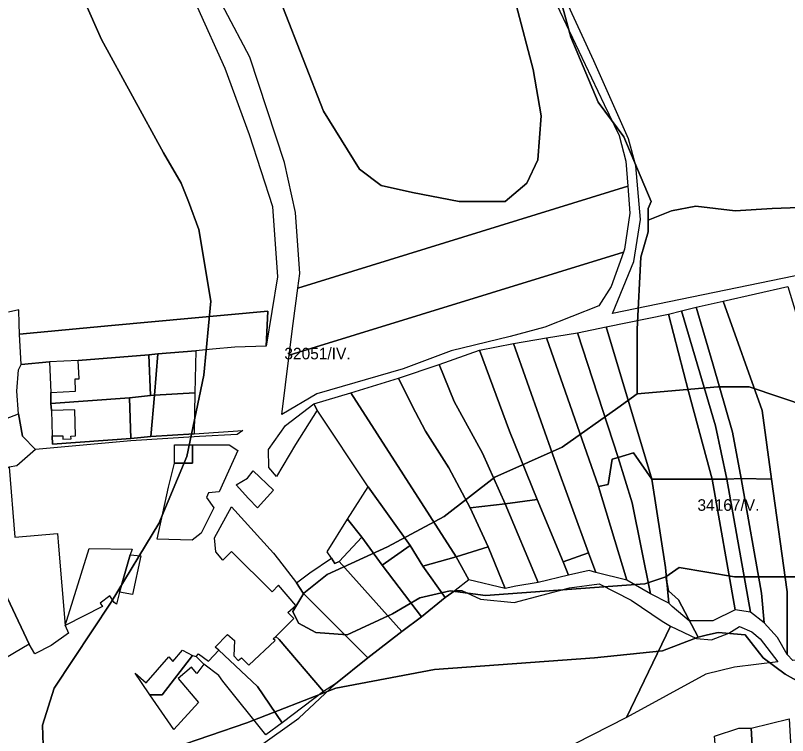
# Model space of a CAD drawing. Extents: x -532083 to -529270, y -1180561 to -1176456.
# Drawn here: x -531885.3 to -531552, y -1178230.5 to -1177919.6 of the extents above; entities that cross this region are included whole.
import ezdxf

# ---------------------------------------------------------------- set-up
doc = ezdxf.new("R2010")
doc.units = 0
for name, color, linetype in [('95560013', 7, 'Continuous'), ('95590013', 7, 'Continuous'), ('95610013', 7, 'Continuous'), ('95660013', 7, 'Continuous')]:
    doc.layers.add(name, color=color, linetype=linetype)

msp = doc.modelspace()

# ---------------------------------------------------------------- linework, layer by layer
at = {"layer": '95560013'}
for points in [[(-531424.6003, -1177849.79445), (-531429.9573, -1177919.79245), (-531429.9573, -1177963.95745), (-531425.3063, -1178000.34745), (-531424.6863, -1178005.32445), (-531490.1123, -1178018.25145), (-531539.5053, -1178030.11045), (-531627.5183, -1178048.29445), (-531618.3223, -1178025.89345), (-531615.4323, -1178007.71045), (-531617.5343, -1177984.51945), (-531620.6873, -1177972.92345), (-531635.6623, -1177939.19145), (-531648.2733, -1177911.52045)], [(-531806.8203, -1177915.90545), (-531794.8753, -1177942.31245), (-531784.4443, -1177970.98845), (-531774.3943, -1178002.04445), (-531772.2003, -1178032.42445), (-531777.0283, -1178062.36345), (-531776.2963, -1178047.24745), (-531843.8873, -1178053.43645), (-531883.5303, -1178057.25145), (-531883.6763, -1178052.70245), (-531883.8673, -1178046.75645), (-531888.2813, -1178047.78945)]]:
    msp.add_lwpolyline(points, dxfattribs=at)
for points in [[(-531633.5823, -1178122.95245), (-531656.0973, -1178058.76345), (-531642.7123, -1178056.59445), (-531625.1133, -1178110.40845), (-531627.7023, -1178111.15745), (-531629.4663, -1178122.16545)], [(-531836.0653, -1178084.78645), (-531869.9413, -1178087.19945), (-531869.9983, -1178082.36545), (-531859.3073, -1178081.88145), (-531859.5493, -1178076.52245), (-531857.8333, -1178076.44445), (-531858.1913, -1178068.55145), (-531827.6463, -1178066.08745), (-531827.0453, -1178083.78145)], [(-531807.8023, -1178082.57445), (-531825.2413, -1178083.58045), (-531823.8383, -1178065.68545), (-531807.4013, -1178064.47845)], [(-531826.8443, -1178101.47545), (-531835.4643, -1178102.27945), (-531836.0653, -1178084.78645), (-531827.0453, -1178083.78145), (-531825.2413, -1178083.58045)], [(-531808.2023, -1178100.26845), (-531826.8443, -1178101.47545), (-531825.2413, -1178083.58045), (-531807.8023, -1178082.57445)], [(-531835.4643, -1178102.27945), (-531869.3403, -1178104.69245), (-531869.3973, -1178101.18845), (-531864.9013, -1178101.06545), (-531864.8613, -1178102.54245), (-531861.2943, -1178102.44545), (-531861.3283, -1178101.19745), (-531859.3323, -1178101.14345), (-531859.6393, -1178089.92145), (-531869.6983, -1178090.19545), (-531869.9413, -1178087.19945), (-531836.0653, -1178084.78645)]]:
    msp.add_lwpolyline(points, close=True, dxfattribs=at)
at = {"layer": '95590013'}
for points in [[(-531558.9753, -1178119.80545), (-531572.0323, -1178119.52045), (-531575.7223, -1178099.58945), (-531584.2383, -1178069.97645), (-531591.4943, -1178045.51745), (-531579.8623, -1178043.01645), (-531562.9493, -1178090.19245)], [(-531807.4013, -1178064.47845), (-531823.8383, -1178065.68545), (-531827.6463, -1178066.08745), (-531858.1913, -1178068.55145), (-531870.5983, -1178069.11445), (-531882.8463, -1178070.37345), (-531883.5303, -1178057.25145), (-531843.8873, -1178053.43645), (-531776.2963, -1178047.24745), (-531777.0283, -1178062.36345), (-531790.5263, -1178062.82645), (-531800.1913, -1178063.69345)], [(-531584.5223, -1178119.80545), (-531610.6373, -1178119.80545), (-531630.2673, -1178054.12845), (-531603.4033, -1178048.57245), (-531594.7413, -1178081.93545)], [(-531618.5853, -1178108.41545), (-531625.1133, -1178110.40845), (-531642.7123, -1178056.59445), (-531630.2673, -1178054.12845), (-531610.6373, -1178119.80545)], [(-531673.9533, -1178130.42245), (-531683.7643, -1178108.67545), (-531695.9463, -1178086.30845), (-531702.3463, -1178070.36145), (-531685.0033, -1178064.14845), (-531671.9953, -1178099.14845), (-531660.0393, -1178128.65345)], [(-531648.8683, -1178155.58445), (-531660.0393, -1178128.65345), (-531671.9953, -1178099.14845), (-531685.0033, -1178064.14845), (-531670.3443, -1178061.24845), (-531652.5873, -1178111.36745), (-531637.8933, -1178151.65345)], [(-531825.2413, -1178083.58045), (-531827.0453, -1178083.78145), (-531827.6463, -1178066.08745), (-531823.8383, -1178065.68545)], [(-531876.5863, -1178106.95645), (-531882.3023, -1178101.22345), (-531883.9353, -1178091.66845), (-531884.7513, -1178081.83945), (-531883.9353, -1178072.55745), (-531882.8463, -1178070.37345), (-531870.5983, -1178069.11445), (-531869.9983, -1178082.36545), (-531869.9413, -1178087.19945), (-531869.6983, -1178090.19545), (-531869.3973, -1178101.18845), (-531869.3403, -1178104.69245), (-531835.4643, -1178102.27945), (-531826.8443, -1178101.47545), (-531808.2023, -1178100.26845), (-531787.1773, -1178098.75445), (-531789.5383, -1178100.57645), (-531805.7973, -1178101.47545), (-531835.4643, -1178103.28445)], [(-531681.2053, -1178149.09745), (-531695.1193, -1178153.42245), (-531740.5423, -1178082.58045), (-531719.8963, -1178076.16045), (-531714.1153, -1178088.17245), (-531708.3343, -1178099.14845), (-531698.2173, -1178114.88845), (-531689.0443, -1178132.19145)], [(-531709.4263, -1178157.35445), (-531714.9403, -1178148.43845), (-531733.1103, -1178123.17245), (-531754.9953, -1178090.03645), (-531756.4403, -1178087.34345), (-531740.5423, -1178082.58045), (-531695.1193, -1178153.42245)], [(-531912.2403, -1178121.42645), (-531943.5403, -1178133.16545), (-531957.9653, -1178137.80645), (-531968.3253, -1178140.92145), (-531972.2873, -1178128.08345), (-531979.3313, -1178130.25745), (-531975.3683, -1178143.09545), (-531989.5373, -1178147.08845), (-531996.6133, -1178129.61645), (-531923.9443, -1178105.04545), (-531905.1643, -1178099.03945), (-531891.8283, -1178094.67145), (-531887.7453, -1178093.03345), (-531883.9353, -1178091.66845), (-531882.3023, -1178101.22345), (-531876.5863, -1178106.95645), (-531884.7513, -1178114.05445), (-531888.0173, -1178114.60045), (-531899.4483, -1178117.33145)], [(-531808.9713, -1178146.12145), (-531824.1483, -1178145.71645), (-531819.2383, -1178123.31745), (-531816.6083, -1178112.86745), (-531808.9213, -1178112.86745), (-531808.9213, -1178104.95345), (-531792.9893, -1178104.94845), (-531789.3563, -1178107.49945), (-531797.3483, -1178125.35245), (-531801.8883, -1178125.71745), (-531802.7963, -1178127.72145), (-531799.7093, -1178132.27545), (-531805.1573, -1178143.20645)], [(-531808.9213, -1178112.86745), (-531816.6083, -1178112.86745), (-531816.6083, -1178104.95345), (-531808.9213, -1178104.95345)], [(-531621.4313, -1178163.44845), (-531633.5823, -1178122.95245), (-531629.4663, -1178122.16545), (-531627.7023, -1178111.15745), (-531625.1133, -1178110.40845), (-531619.1523, -1178130.05545), (-531611.2043, -1178169.34845)], [(-531611.2043, -1178169.34845), (-531619.1523, -1178130.05545), (-531625.1133, -1178110.40845), (-531618.5853, -1178108.41545), (-531610.6373, -1178119.80545), (-531604.6763, -1178157.95945), (-531603.2563, -1178173.33445)], [(-531879.4333, -1178191.11245), (-531912.2403, -1178121.42645), (-531899.4483, -1178117.33145), (-531888.0173, -1178114.60045), (-531885.5763, -1178144.90545), (-531867.1183, -1178143.26045), (-531866.7063, -1178148.80945), (-531863.7823, -1178183.03145), (-531862.3773, -1178186.29845), (-531869.9033, -1178191.70845), (-531876.8763, -1178195.29845)], [(-531604.6763, -1178157.95945), (-531610.6373, -1178119.80545), (-531584.5223, -1178119.80545), (-531574.5873, -1178176.18145), (-531584.2383, -1178181.02245), (-531594.4573, -1178181.02245), (-531601.8373, -1178174.75845), (-531603.2563, -1178173.33445)], [(-531574.5873, -1178176.18145), (-531584.5223, -1178119.80545), (-531578.2773, -1178119.80545), (-531568.0583, -1178177.32045)], [(-531568.0583, -1178177.32045), (-531578.2773, -1178119.80545), (-531572.0323, -1178119.52045), (-531563.2323, -1178169.06345), (-531562.0973, -1178181.87645)], [(-531563.2323, -1178169.06345), (-531572.0323, -1178119.52045), (-531558.9753, -1178119.80545), (-531552.1623, -1178168.49445), (-531552.1623, -1178195.54345), (-531556.4203, -1178188.14045), (-531562.0973, -1178181.87645)], [(-531879.4333, -1178191.11245), (-531903.0633, -1178205.09745), (-531924.6193, -1178170.74745), (-531929.2293, -1178162.13145), (-531943.5403, -1178133.16545), (-531912.2403, -1178121.42645)], [(-531673.9533, -1178166.98645), (-531681.2053, -1178149.09745), (-531689.0443, -1178132.19145), (-531673.9533, -1178130.42245), (-531659.6473, -1178164.43045), (-531669.2503, -1178166.00345)], [(-531659.6473, -1178164.43045), (-531673.9533, -1178130.42245), (-531660.0393, -1178128.65345), (-531648.8683, -1178155.58445), (-531646.5163, -1178161.28545)], [(-531752.3743, -1178211.55845), (-531771.5303, -1178189.07745), (-531772.8423, -1178187.81645), (-531765.1443, -1178180.06045), (-531767.7793, -1178177.44445), (-531764.2333, -1178174.43745), (-531771.7133, -1178165.65445), (-531774.5073, -1178168.43345), (-531792.0313, -1178151.03945), (-531795.8253, -1178154.86245), (-531798.8033, -1178151.21445), (-531799.4213, -1178145.21745), (-531792.0013, -1178131.77745), (-531773.8613, -1178151.83445), (-531771.7993, -1178154.52245), (-531763.9663, -1178164.65445), (-531761.0803, -1178168.99645), (-531733.1243, -1178196.99145), (-531747.1753, -1178208.14145)], [(-531718.4433, -1178185.63145), (-531745.6203, -1178155.34945), (-531735.7263, -1178144.80445), (-531727.0683, -1178157.00345), (-531710.0543, -1178179.32045)], [(-531842.6593, -1178173.02345), (-531844.5553, -1178170.24045), (-531848.6923, -1178173.35245), (-531847.6573, -1178174.77845), (-531863.7823, -1178183.03145), (-531853.4413, -1178149.80145), (-531834.8663, -1178149.99345), (-531835.7643, -1178152.47545), (-531840.4183, -1178168.55445), (-531841.7073, -1178173.87245)], [(-531710.0543, -1178179.32045), (-531727.0683, -1178157.00345), (-531714.9403, -1178148.43845), (-531709.4263, -1178157.35445), (-531699.8233, -1178170.91845)], [(-531673.9533, -1178166.98645), (-531689.6323, -1178163.25145), (-531695.1193, -1178153.42245), (-531681.2053, -1178149.09745)], [(-531834.7303, -1178169.59145), (-531840.4183, -1178168.55445), (-531835.7643, -1178152.47545), (-531831.1113, -1178152.99445)], [(-531733.1243, -1178196.99145), (-531761.0803, -1178168.99645), (-531763.9663, -1178164.65445), (-531758.1943, -1178160.31245), (-531748.9183, -1178153.90245), (-531747.4753, -1178156.17645), (-531745.6203, -1178155.34945), (-531718.4433, -1178185.63145)], [(-531699.8233, -1178170.91845), (-531709.4263, -1178157.35445), (-531695.1193, -1178153.42245), (-531689.6323, -1178163.25145), (-531695.5113, -1178167.96945)], [(-531637.6973, -1178159.31945), (-531646.5163, -1178161.28545), (-531648.8683, -1178155.58445), (-531637.8933, -1178151.65345), (-531634.7583, -1178160.10645)], [(-531752.3743, -1178211.55845), (-531770.1043, -1178225.03845), (-531780.8423, -1178209.38045), (-531797.4623, -1178193.62745), (-531799.0333, -1178192.31445), (-531793.7983, -1178186.93245), (-531790.7883, -1178189.55845), (-531791.0503, -1178196.12145), (-531789.0873, -1178198.09045), (-531787.7783, -1178197.04045), (-531784.5063, -1178200.19145), (-531773.1203, -1178189.42645), (-531774.0123, -1178188.81445), (-531772.8423, -1178187.81645), (-531771.5303, -1178189.07745)], [(-531808.8543, -1178196.01345), (-531821.9463, -1178212.99045), (-531827.2243, -1178212.99045), (-531830.9113, -1178207.69145), (-531833.6303, -1178203.57245), (-531828.7933, -1178207.75145), (-531819.0633, -1178196.49045), (-531817.3603, -1178198.54545), (-531813.1523, -1178193.67245)], [(-531777.1963, -1178230.28045), (-531795.7613, -1178207.11845), (-531797.4643, -1178204.55545), (-531803.9573, -1178199.64445), (-531807.2573, -1178196.33445), (-531806.2803, -1178195.29645), (-531801.9733, -1178198.41145), (-531797.4623, -1178193.62745), (-531780.8423, -1178209.38045), (-531770.1043, -1178225.03845)], [(-531816.8873, -1178227.84945), (-531827.2243, -1178212.99045), (-531821.9463, -1178212.99045), (-531808.8543, -1178196.01345), (-531807.2573, -1178196.33445), (-531803.9573, -1178199.64445), (-531807.0513, -1178203.70045), (-531809.3103, -1178201.03145), (-531815.0423, -1178205.88245), (-531806.2323, -1178216.29345)], [(-531578.2013, -1178293.39745), (-531583.5583, -1178230.78545), (-531573.0133, -1178227.32745), (-531567.7413, -1178227.32745), (-531563.8583, -1178294.79645), (-531566.0493, -1178294.99645), (-531573.4203, -1178293.59745)]]:
    msp.add_lwpolyline(points, close=True, dxfattribs=at)
at = {"layer": '95610013'}
for points in [[(-531653.0833, -1177911.86445), (-531631.1683, -1177958.12845), (-531624.6473, -1177971.46345), (-531621.8873, -1177982.53445), (-531621.0353, -1177993.40045), (-531763.4063, -1178037.30445), (-531762.5543, -1178030.99145), (-531764.3573, -1178004.76845), (-531769.1993, -1177983.08345), (-531784.1913, -1177937.69645), (-531805.7253, -1177896.68445)], [(-531780.5213, -1178235.48945), (-531762.9043, -1178223.07745), (-531747.1753, -1178208.14145), (-531733.1243, -1178196.99145), (-531718.4433, -1178185.63145), (-531710.0543, -1178179.32045), (-531699.8233, -1178170.91845), (-531695.5113, -1178167.96945), (-531692.5713, -1178167.96945), (-531684.5363, -1178171.70445), (-531670.0343, -1178173.08045), (-531646.1243, -1178166.78945), (-531633.3863, -1178165.02045), (-531619.4713, -1178172.09745), (-531606.1213, -1178181.13245), (-531602.6103, -1178183.33445), (-531621.4833, -1178222.74045), (-531665.8023, -1178245.37645)]]:
    msp.add_lwpolyline(points, dxfattribs=at)
for points in [[(-531622.8643, -1178021.85045), (-531767.1833, -1178066.35645), (-531765.4843, -1178052.69345), (-531763.4063, -1178037.30445), (-531621.0353, -1177993.40045), (-531620.1323, -1178004.92645), (-531622.3893, -1178020.52545)], [(-531671.8033, -1178058.26645), (-531697.2243, -1178064.43145), (-531717.8893, -1178072.12745), (-531755.2593, -1178083.05045), (-531770.3563, -1178091.86345), (-531767.1833, -1178066.35645), (-531622.8643, -1178021.85045), (-531628.1583, -1178036.62845), (-531633.4263, -1178044.93145), (-531656.7533, -1178054.24045)], [(-531552.1623, -1178168.49445), (-531558.9753, -1178119.80545), (-531562.9493, -1178090.19245), (-531579.8623, -1178043.01645), (-531551.8913, -1178036.62745), (-531534.5243, -1178093.95245), (-531527.0293, -1178128.35245), (-531522.2603, -1178173.46045), (-531521.3513, -1178196.24145), (-531549.7413, -1178198.06445), (-531552.1623, -1178195.54345)], [(-531584.5223, -1178119.80545), (-531594.7413, -1178081.93545), (-531603.4033, -1178048.57245), (-531597.8643, -1178047.18345), (-531583.1023, -1178096.74145), (-531578.2773, -1178119.80545)], [(-531578.2773, -1178119.80545), (-531583.1023, -1178096.74145), (-531597.8643, -1178047.18345), (-531591.4943, -1178045.51745), (-531584.2383, -1178069.97645), (-531575.7223, -1178099.58945), (-531572.0323, -1178119.52045)], [(-531637.8933, -1178151.65345), (-531652.5873, -1178111.36745), (-531670.3443, -1178061.24845), (-531656.0973, -1178058.76345), (-531633.5823, -1178122.95245), (-531621.4313, -1178163.44845), (-531634.7583, -1178160.10645)], [(-531673.9533, -1178130.42245), (-531689.0443, -1178132.19145), (-531698.2173, -1178114.88845), (-531708.3343, -1178099.14845), (-531714.1153, -1178088.17245), (-531719.8963, -1178076.16045), (-531702.3463, -1178070.36145), (-531695.9463, -1178086.30845), (-531683.7643, -1178108.67545)], [(-531764.3793, -1178104.89745), (-531772.6243, -1178118.75145), (-531775.9223, -1178114.82245), (-531776.1283, -1178106.96545), (-531768.7073, -1178096.62645), (-531756.4403, -1178087.34345), (-531754.9953, -1178090.03645)], [(-531780.8333, -1178132.20845), (-531784.7213, -1178128.19645), (-531790.0843, -1178122.22345), (-531785.1773, -1178119.41045), (-531782.6543, -1178116.17645), (-531773.8333, -1178124.63045)], [(-531727.0683, -1178157.00345), (-531735.7263, -1178144.80445), (-531741.9103, -1178137.15345), (-531733.1103, -1178123.17245), (-531714.9403, -1178148.43845)], [(-531745.6203, -1178155.34945), (-531747.4753, -1178156.17645), (-531748.9183, -1178153.90245), (-531750.7743, -1178151.21445), (-531741.9103, -1178137.15345), (-531735.7263, -1178144.80445)], [(-531587.3503, -1178204.07845), (-531621.4833, -1178222.74045), (-531602.6103, -1178183.33445), (-531591.2723, -1178188.57145), (-531584.8123, -1178189.26645), (-531577.4283, -1178186.25745), (-531572.8133, -1178183.48045), (-531567.5063, -1178185.79445), (-531563.8153, -1178188.80345), (-531556.2003, -1178198.75545), (-531574.8903, -1178201.06945)], [(-531547.3243, -1178294.39645), (-531563.8583, -1178294.79645), (-531567.7413, -1178227.32745), (-531551.3173, -1178223.25945)]]:
    msp.add_lwpolyline(points, close=True, dxfattribs=at)
at = {"layer": '95660013'}
for points in [[(-531658.6253, -1177881.00045), (-531645.5003, -1177929.00045), (-531633.8123, -1177957.00045), (-531622.6253, -1177972.00045), (-531610.8753, -1178000.00045), (-531612.1873, -1178003.00045), (-531612.1873, -1178008.00045), (-531612.1873, -1178013.00045), (-531615.3123, -1178024.00045), (-531617.0003, -1178055.00045), (-531617.0003, -1178083.00045), (-531625.3123, -1178089.00045), (-531649.3123, -1178106.00045), (-531678.3753, -1178119.00045), (-531700.3123, -1178136.00045), (-531724.6873, -1178149.00045), (-531750.8123, -1178161.00045), (-531760.8753, -1178169.00045), (-531765.6253, -1178177.00045), (-531763.1253, -1178182.00045), (-531755.6253, -1178186.00045), (-531742.1253, -1178187.00045), (-531722.5003, -1178178.00045), (-531710.6873, -1178171.00045), (-531697.6253, -1178168.00045), (-531682.3753, -1178170.00045), (-531641.1873, -1178167.00045), (-531613.6873, -1178165.00045), (-531604.6253, -1178162.00045), (-531603.3753, -1178168.00045), (-531599.1253, -1178172.00045), (-531590.6253, -1178188.00045), (-531606.0003, -1178194.00045), (-531635.3753, -1178197.00045), (-531704.3753, -1178202.00045), (-531747.0003, -1178210.00045), (-531785.3753, -1178225.00045), (-531817.3753, -1178236.00045)], [(-531531.5003, -1178002.00045), (-531558.6253, -1178003.00045), (-531574.6873, -1178004.00045), (-531591.6873, -1178002.00045), (-531602.1253, -1178004.00045), (-531612.1873, -1178008.00045), (-531612.1873, -1178003.00045), (-531610.8753, -1178000.00045), (-531622.6253, -1177972.00045), (-531633.8123, -1177957.00045), (-531645.5003, -1177929.00045), (-531658.6253, -1177881.00045)], [(-531873.1253, -1178239.00045), (-531873.6253, -1178226.00045), (-531868.6253, -1178210.00045), (-531844.0003, -1178173.00045), (-531823.3753, -1178139.00045), (-531811.3753, -1178110.00045), (-531804.0003, -1178075.00045), (-531801.0003, -1178043.00045), (-531806.1873, -1178012.00045), (-531810.6253, -1178000.00045), (-531813.8123, -1177992.00045), (-531821.3123, -1177979.00045), (-531848.1253, -1177930.00045), (-531862.1873, -1177898.00045)], [(-531862.1873, -1177898.00045), (-531848.1253, -1177930.00045), (-531821.3123, -1177979.00045), (-531813.8123, -1177992.00045), (-531810.6253, -1178000.00045), (-531806.1873, -1178012.00045), (-531801.0003, -1178043.00045), (-531804.0003, -1178075.00045), (-531811.3753, -1178110.00045), (-531823.3753, -1178139.00045), (-531844.0003, -1178173.00045), (-531868.6253, -1178210.00045), (-531873.6253, -1178226.00045), (-531873.1253, -1178239.00045)], [(-531769.8123, -1177916.00045), (-531752.3123, -1177961.00045), (-531736.8123, -1177986.00045), (-531727.3753, -1177993.00045), (-531713.8753, -1177996.00045), (-531693.8123, -1178000.00045), (-531673.8753, -1178000.00045), (-531664.5003, -1177992.00045), (-531659.8123, -1177982.00045), (-531658.3753, -1177963.00045), (-531661.8123, -1177943.00045), (-531669.1873, -1177915.00045)], [(-531669.1873, -1177915.00045), (-531661.8123, -1177943.00045), (-531658.3753, -1177963.00045), (-531659.8123, -1177982.00045), (-531664.5003, -1177992.00045), (-531673.8753, -1178000.00045), (-531693.8123, -1178000.00045), (-531713.8753, -1177996.00045), (-531727.3753, -1177993.00045), (-531736.8123, -1177986.00045), (-531752.3123, -1177961.00045), (-531769.8123, -1177916.00045)], [(-531529.8123, -1178093.00045), (-531568.6253, -1178080.00045), (-531582.1253, -1178080.00045), (-531617.0003, -1178083.00045), (-531617.0003, -1178055.00045), (-531615.3123, -1178024.00045), (-531612.1873, -1178013.00045), (-531612.1873, -1178008.00045), (-531602.1253, -1178004.00045), (-531591.6873, -1178002.00045), (-531574.6873, -1178004.00045), (-531558.6253, -1178003.00045), (-531531.5003, -1178002.00045)], [(-531546.6253, -1178162.00045), (-531574.8753, -1178162.00045), (-531598.8753, -1178158.00045), (-531604.6253, -1178162.00045), (-531613.6873, -1178165.00045), (-531641.1873, -1178167.00045), (-531682.3753, -1178170.00045), (-531697.6253, -1178168.00045), (-531710.6873, -1178171.00045), (-531722.5003, -1178178.00045), (-531742.1253, -1178187.00045), (-531755.6253, -1178186.00045), (-531763.1253, -1178182.00045), (-531765.6253, -1178177.00045), (-531760.8753, -1178169.00045), (-531750.8123, -1178161.00045), (-531724.6873, -1178149.00045), (-531700.3123, -1178136.00045), (-531678.3753, -1178119.00045), (-531649.3123, -1178106.00045), (-531625.3123, -1178089.00045), (-531617.0003, -1178083.00045), (-531582.1253, -1178080.00045), (-531568.6253, -1178080.00045), (-531529.8123, -1178093.00045)], [(-531545.8123, -1178208.00045), (-531553.1253, -1178204.00045), (-531562.6253, -1178197.00045), (-531570.3753, -1178187.00045), (-531582.0003, -1178186.00045), (-531586.6253, -1178187.00045), (-531590.6253, -1178188.00045), (-531599.1253, -1178172.00045), (-531603.3753, -1178168.00045), (-531604.6253, -1178162.00045), (-531598.8753, -1178158.00045), (-531574.8753, -1178162.00045), (-531546.6253, -1178162.00045)], [(-531817.3753, -1178236.00045), (-531785.3753, -1178225.00045), (-531747.0003, -1178210.00045), (-531704.3753, -1178202.00045), (-531635.3753, -1178197.00045), (-531606.0003, -1178194.00045), (-531590.6253, -1178188.00045), (-531586.6253, -1178187.00045), (-531582.0003, -1178186.00045), (-531570.3753, -1178187.00045), (-531562.6253, -1178197.00045), (-531553.1253, -1178204.00045), (-531545.8123, -1178208.00045)]]:
    msp.add_lwpolyline(points, dxfattribs=at)

# ---------------------------------------------------------------- texts
for s, rotation, p in [('32051/IV.', 0, (-531769.2188, -1178068.1059)), ('34167/V.', 360, (-531590.92585, -1178133.50045))]:
    msp.add_text(s, height=5, rotation=rotation, dxfattribs=at).set_placement(p)

doc.saveas('drawing.dxf')
